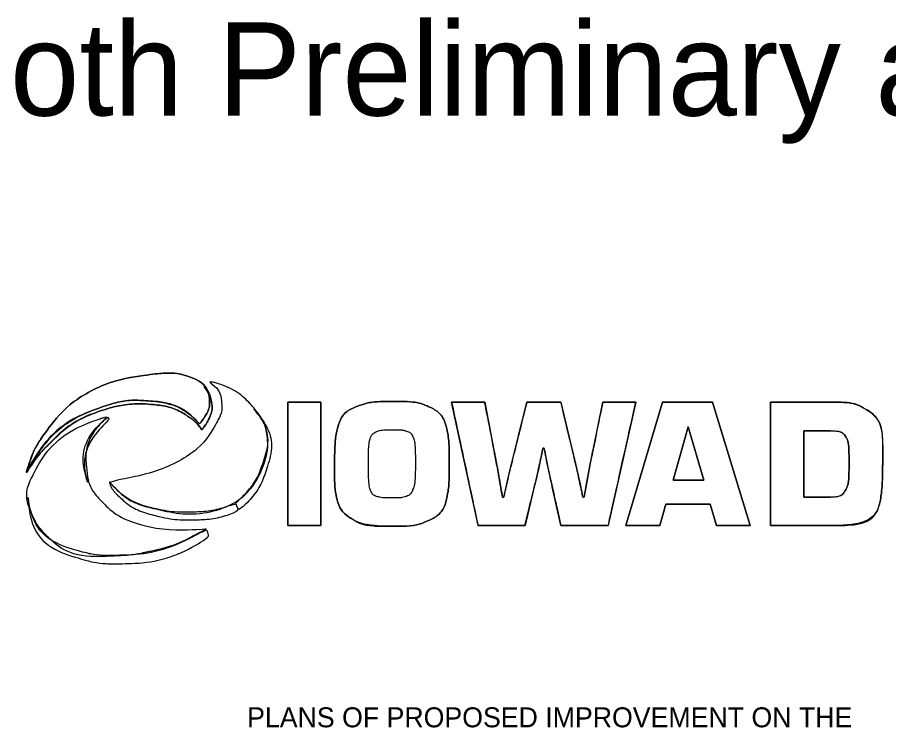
# Model space of a CAD drawing. Extents: x 10196 to 23010, y 6417 to 10189.
# Drawn here: x 11284 to 11939, y 9655 to 10189 of the extents above; entities that cross this region are included whole.
import ezdxf

# ---------------------------------------------------------------- set-up
doc = ezdxf.new("R2010")
doc.units = 0
doc.layers.add('dsnDOTLogo', color=7, linetype='Continuous')
doc.layers.add('Level 1', color=7, linetype='Continuous')

msp = doc.modelspace()

# ---------------------------------------------------------------- linework, layer by layer
at = {"layer": 'dsnDOTLogo'}
for p, q in [((11630.53, 9807.22), (11610.74, 9899.72)), ((11610.74, 9899.72), (11635.62, 9899.72)), ((11635.62, 9899.72), (11642.48, 9864.08)), ((11653.84, 9846.25), (11667.25, 9899.72)), ((11667.25, 9899.72), (11692.8, 9899.72)), ((11692.8, 9899.72), (11701.34, 9864.08)), ((11716.99, 9864.08), (11724.24, 9899.72)), ((11724.24, 9899.72), (11749.04, 9899.72)), ((11749.04, 9899.72), (11728.44, 9807.22)), ((11850.38, 9807.22), (11850.38, 9899.72)), ((11850.38, 9899.72), (11898.75, 9899.72)), ((11420.59, 9884.21), (11421.27, 9883.48)), ((11421.27, 9883.48), (11420.59, 9884.21)), ((11421.27, 9883.48), (11421.91, 9884.25)), ((11421.91, 9884.25), (11421.27, 9883.48)), ((11423.02, 9878.95), (11423.14, 9879.1)), ((11423.14, 9879.1), (11423.54, 9879.6)), ((11423.91, 9880.04), (11424.1, 9880.29)), ((11424.1, 9880.29), (11424.1, 9880.32)), ((11424.52, 9880.92), (11424.54, 9880.9)), ((11424.54, 9880.9), (11424.53, 9880.94)), ((11895.4, 9878.17), (11875.31, 9878.17)), ((11875.31, 9878.17), (11875.31, 9828.5)), ((11307.37, 9867.39), (11307.37, 9867.37)), ((11680.25, 9865.16), (11679.32, 9865.16)), ((11934.61, 9865.23), (11934.61, 9854.18)), ((11716.58, 9862.18), (11716.99, 9864.08)), ((11293.8, 9855.21), (11291.27, 9847.78)), ((11291.27, 9847.78), (11295.38, 9854.47)), ((11295.38, 9854.47), (11291.27, 9847.78)), ((11291.27, 9847.78), (11291.27, 9846.94)), ((11649.84, 9828.43), (11653.84, 9846.25)), ((11672.84, 9836.22), (11665.85, 9807.22)), ((11692.77, 9807.22), (11686.34, 9836.23)), ((11648.89, 9828.43), (11649.84, 9828.43)), ((11709.33, 9828.43), (11710.28, 9828.43)), ((11875.31, 9828.5), (11895.33, 9828.5)), ((11665.85, 9807.22), (11630.53, 9807.22)), ((11728.44, 9807.22), (11692.77, 9807.22)), ((11897.47, 9807.22), (11850.38, 9807.22))]:
    msp.add_line(p, q, dxfattribs=at)
for points in [[(11512.48, 9807.22), (11512.48, 9899.72), (11487.54, 9899.72), (11487.54, 9807.22), (11512.48, 9807.22)], [(11512.48, 9899.72), (11512.48, 9807.22), (11487.54, 9807.22), (11487.54, 9899.72), (11512.48, 9899.72)], [(11804.95, 9823.15), (11771.67, 9823.15), (11767.24, 9807.22), (11741.49, 9807.22), (11769.27, 9899.72), (11806.81, 9899.72), (11834.94, 9807.22), (11809.72, 9807.22), (11804.95, 9823.15)], [(11834.94, 9807.22), (11806.81, 9899.72), (11769.27, 9899.72), (11741.49, 9807.22), (11767.24, 9807.22), (11771.67, 9823.15), (11804.95, 9823.15), (11809.72, 9807.22), (11834.94, 9807.22)], [(11777.07, 9841.1), (11788.42, 9881.25), (11800.13, 9841.1), (11777.07, 9841.1)], [(11800.13, 9841.1), (11788.42, 9881.25), (11777.07, 9841.1), (11800.13, 9841.1)]]:
    msp.add_lwpolyline(points, dxfattribs=at)
for points, degree in [([(11408.05, 9920.61), (11402.55, 9921.77), (11394.73, 9921.8), (11385.55, 9920.67), (11353.84, 9916.5), (11321.5, 9898.71), (11305.08, 9876.41), (11300.05, 9869.58), (11296.26, 9862.44), (11293.8, 9855.21), (11293.8, 9855.21), (11291.27, 9847.78), (11291.27, 9847.78), (11291.27, 9847.78), (11295.38, 9854.47), (11295.38, 9854.47), (11306.66, 9872.85), (11325.79, 9888.23), (11346.55, 9895.62), (11358.24, 9899.79), (11370.7, 9901.62), (11382.08, 9900.82), (11397.68, 9899.74), (11411.72, 9893.68), (11420.59, 9884.21), (11420.59, 9884.21), (11421.27, 9883.48), (11421.27, 9883.48), (11421.27, 9883.48), (11421.91, 9884.25), (11421.91, 9884.25), (11423.3, 9885.94), (11424.49, 9887.63), (11425.45, 9889.26), (11427.91, 9893.41), (11429.05, 9897.51), (11428.83, 9901.52), (11427.94, 9910.33), (11420.38, 9917.29), (11408.05, 9920.61)], 3), ([(11408.05, 9920.61), (11402.55, 9921.77), (11394.73, 9921.8), (11385.55, 9920.67), (11353.84, 9916.5), (11321.5, 9898.71), (11305.08, 9876.41), (11300.05, 9869.58), (11296.26, 9862.44), (11293.8, 9855.21)], 3), ([(11421.91, 9884.25), (11423.3, 9885.94), (11424.49, 9887.63), (11425.45, 9889.26), (11427.91, 9893.41), (11429.05, 9897.51), (11428.83, 9901.52), (11427.94, 9910.33), (11420.38, 9917.29), (11408.05, 9920.61)], 3), ([(11429.91, 9901.61), (11429.91, 9901.61), (11429.12, 9907.3), (11423.22, 9912.63), (11426.46, 9909.47), (11428.41, 9905.71), (11428.83, 9901.52), (11429.05, 9897.51), (11427.91, 9893.41), (11425.45, 9889.26), (11424.49, 9887.63), (11423.3, 9885.94), (11421.91, 9884.25), (11421.91, 9884.25), (11421.27, 9883.48), (11421.27, 9883.48), (11421.27, 9883.48), (11420.59, 9884.21), (11420.59, 9884.21), (11411.72, 9893.68), (11397.68, 9899.74), (11382.08, 9900.82), (11370.7, 9901.62), (11358.24, 9899.79), (11346.55, 9895.62), (11325.79, 9888.23), (11306.66, 9872.85), (11295.38, 9854.47), (11295.38, 9854.47), (11291.27, 9847.78), (11291.27, 9847.78), (11291.27, 9847.78), (11291.27, 9846.94), (11291.27, 9846.94), (11291.27, 9846.94), (11300.26, 9860.62), (11307.37, 9867.39), (11307.37, 9867.39), (11307.37, 9867.37), (11307.37, 9867.37), (11318.04, 9878.55), (11331.79, 9887.9), (11347, 9893.23), (11352.61, 9895.19), (11358.22, 9896.6), (11363.71, 9897.45), (11370.58, 9898.51), (11377.3, 9898.74), (11383.69, 9898.21), (11395.52, 9897.22), (11406.41, 9893.47), (11415.07, 9887.49), (11415.96, 9886.79), (11419.92, 9883.56), (11423.02, 9878.95), (11423.02, 9878.95), (11423.14, 9879.1), (11423.14, 9879.1), (11423.14, 9879.1), (11423.54, 9879.6), (11423.54, 9879.6), (11423.55, 9879.59), (11423.55, 9879.58), (11423.56, 9879.57), (11423.68, 9879.73), (11423.79, 9879.88), (11423.91, 9880.04), (11423.91, 9880.04), (11424.1, 9880.29), (11424.1, 9880.29), (11424.1, 9880.29), (11424.1, 9880.32), (11424.1, 9880.32), (11424.25, 9880.52), (11424.38, 9880.72), (11424.52, 9880.92), (11424.52, 9880.92), (11424.54, 9880.9), (11424.54, 9880.9), (11424.54, 9880.9), (11424.53, 9880.94), (11424.53, 9880.94), (11425.45, 9882.23), (11426.31, 9883.52), (11427.03, 9884.83), (11430.37, 9890.84), (11431.24, 9896.57), (11429.91, 9901.61)], 3), ([(11469.85, 9853.83), (11466.08, 9843.07), (11458.77, 9832.97), (11448.77, 9823.93), (11429.81, 9816.48), (11408.33, 9815.06), (11389.33, 9819.38), (11376.53, 9822.3), (11365.46, 9827.73), (11357.58, 9835.58), (11355.99, 9837.13), (11354.61, 9838.76), (11353.36, 9840.44), (11389.24, 9846.17), (11423.04, 9864.23), (11434.79, 9885.6), (11437.36, 9890.29), (11438.33, 9894.85), (11437.88, 9899.05), (11437.43, 9906.05), (11433.09, 9912.13), (11425.63, 9916.37), (11441.55, 9912.25), (11454.42, 9904.45), (11462.42, 9894.95), (11467.98, 9888.34), (11471.45, 9880.48), (11472.3, 9872), (11472.76, 9866.17), (11472.01, 9860.04), (11469.85, 9853.83)], 3), ([(11469.85, 9853.83), (11466.08, 9843.07), (11458.77, 9832.97), (11448.77, 9823.93), (11429.81, 9816.48), (11408.33, 9815.06), (11389.33, 9819.38), (11376.53, 9822.3), (11365.46, 9827.73), (11357.58, 9835.58), (11355.99, 9837.13), (11354.61, 9838.76), (11353.36, 9840.44), (11389.24, 9846.17), (11423.04, 9864.23), (11434.79, 9885.6), (11437.36, 9890.29), (11438.33, 9894.85), (11437.88, 9899.05), (11437.43, 9906.05), (11433.09, 9912.13), (11425.63, 9916.37), (11441.55, 9912.25), (11454.42, 9904.45), (11462.42, 9894.95), (11467.98, 9888.34), (11471.45, 9880.48), (11472.3, 9872), (11472.76, 9866.17), (11472.01, 9860.04), (11469.85, 9853.83)], 3), ([(11429.91, 9901.61), (11429.91, 9901.61), (11429.12, 9907.3), (11423.22, 9912.63), (11426.46, 9909.47), (11428.41, 9905.71), (11428.83, 9901.52), (11429.05, 9897.51), (11427.91, 9893.41), (11425.45, 9889.26), (11424.49, 9887.63), (11423.3, 9885.94), (11421.91, 9884.25)], 3), ([(11295.38, 9854.47), (11306.66, 9872.85), (11325.79, 9888.23), (11346.55, 9895.62), (11358.24, 9899.79), (11370.7, 9901.62), (11382.08, 9900.82), (11397.68, 9899.74), (11411.72, 9893.68), (11420.59, 9884.21)], 3), ([(11420.59, 9884.21), (11411.72, 9893.68), (11397.68, 9899.74), (11382.08, 9900.82), (11370.7, 9901.62), (11358.24, 9899.79), (11346.55, 9895.62), (11325.79, 9888.23), (11306.66, 9872.85), (11295.38, 9854.47)], 3), ([(11307.37, 9867.37), (11318.04, 9878.55), (11331.79, 9887.9), (11347, 9893.23), (11352.61, 9895.19), (11358.22, 9896.6), (11363.71, 9897.45), (11370.58, 9898.51), (11377.3, 9898.74), (11383.69, 9898.21), (11395.52, 9897.22), (11406.41, 9893.47), (11415.07, 9887.49), (11415.96, 9886.79), (11419.92, 9883.56), (11423.02, 9878.95)], 3), ([(11424.53, 9880.94), (11425.45, 9882.23), (11426.31, 9883.52), (11427.03, 9884.83), (11430.37, 9890.84), (11431.24, 9896.57), (11429.91, 9901.61)], 3), ([(11550.16, 9807.39), (11544.37, 9808.2), (11539.86, 9809.59), (11536.64, 9811.56), (11529.68, 9815.85), (11525.39, 9822.24), (11523.76, 9830.74), (11523.09, 9834.3), (11522.75, 9840.25), (11522.75, 9848.56), (11522.75, 9864.1), (11523.56, 9874.78), (11525.19, 9880.61), (11527.45, 9888.7), (11533.39, 9894.43), (11543.01, 9897.82), (11547.8, 9899.54), (11555.88, 9900.4), (11567.27, 9900.4)], 3), ([(11567.27, 9900.4), (11578.65, 9900.4), (11586.78, 9899.33), (11591.66, 9897.21), (11600.34, 9893.42), (11605.67, 9886.66), (11607.65, 9876.95), (11608.47, 9872.97), (11608.87, 9864.98), (11608.87, 9852.96), (11608.87, 9842.89), (11608.56, 9836), (11607.93, 9832.29), (11606.12, 9821.72), (11601.1, 9814.52), (11592.88, 9810.68), (11587.01, 9807.92), (11577.43, 9806.54), (11564.15, 9806.54), (11551.28, 9806.54), (11542.11, 9808.22), (11536.64, 9811.56), (11529.68, 9815.85), (11525.39, 9822.24), (11523.76, 9830.74), (11523.09, 9834.3), (11522.75, 9840.25), (11522.75, 9848.56), (11522.75, 9864.1), (11523.56, 9874.78), (11525.19, 9880.61), (11527.45, 9888.7), (11533.39, 9894.43), (11543.01, 9897.82), (11547.8, 9899.54), (11555.88, 9900.4), (11567.27, 9900.4)], 3), ([(11567.27, 9900.4), (11578.65, 9900.4), (11586.78, 9899.33), (11591.66, 9897.21), (11600.34, 9893.42), (11605.67, 9886.66), (11607.65, 9876.95), (11608.47, 9872.97), (11608.87, 9864.98), (11608.87, 9852.96), (11608.87, 9842.89), (11608.56, 9836), (11607.93, 9832.29), (11606.12, 9821.72), (11601.1, 9814.52), (11592.88, 9810.68), (11587.01, 9807.92), (11577.43, 9806.54), (11564.15, 9806.54), (11558.86, 9806.54), (11554.2, 9806.83), (11550.16, 9807.39)], 3), ([(11749.04, 9899.72), (11749.04, 9899.72), (11728.44, 9807.22), (11728.44, 9807.22), (11728.44, 9807.22), (11692.77, 9807.22), (11692.77, 9807.22), (11692.77, 9807.22), (11686.34, 9836.23), (11686.34, 9836.23), (11684.38, 9844.95), (11682.34, 9854.59), (11680.25, 9865.16), (11680.25, 9865.16), (11679.32, 9865.16), (11679.32, 9865.16), (11678.65, 9862.17), (11678.14, 9859.75), (11677.79, 9857.9), (11676.97, 9853.79), (11675.32, 9846.56), (11672.84, 9836.22), (11672.84, 9836.22), (11665.85, 9807.22), (11665.85, 9807.22), (11665.85, 9807.22), (11630.53, 9807.22), (11630.53, 9807.22), (11630.53, 9807.22), (11610.74, 9899.72), (11610.74, 9899.72), (11610.74, 9899.72), (11635.62, 9899.72), (11635.62, 9899.72), (11635.62, 9899.72), (11642.48, 9864.08), (11642.48, 9864.08), (11644.87, 9851.57), (11647, 9839.68), (11648.89, 9828.43), (11648.89, 9828.43), (11649.84, 9828.43), (11649.84, 9828.43), (11649.84, 9828.43), (11653.84, 9846.25), (11653.84, 9846.25), (11653.84, 9846.25), (11667.25, 9899.72), (11667.25, 9899.72), (11667.25, 9899.72), (11692.8, 9899.72), (11692.8, 9899.72), (11692.8, 9899.72), (11701.34, 9864.08), (11701.34, 9864.08), (11704.09, 9852.6), (11706.76, 9840.72), (11709.33, 9828.43), (11709.33, 9828.43), (11710.28, 9828.43), (11710.28, 9828.43), (11712.23, 9839.68), (11714.32, 9850.93), (11716.58, 9862.18), (11716.58, 9862.18), (11716.99, 9864.08), (11716.99, 9864.08), (11716.99, 9864.08), (11724.24, 9899.72), (11724.24, 9899.72), (11724.24, 9899.72), (11749.04, 9899.72), (11749.04, 9899.72)], 3), ([(11850.38, 9807.22), (11850.38, 9807.22), (11850.38, 9899.72), (11850.38, 9899.72), (11850.38, 9899.72), (11898.75, 9899.72), (11898.75, 9899.72), (11908.36, 9899.72), (11915.77, 9898.14), (11921.01, 9894.98), (11930.25, 9889.42), (11934.78, 9879.5), (11934.61, 9865.23), (11934.61, 9865.23), (11934.61, 9854.18), (11934.61, 9854.18), (11934.47, 9842.84), (11934.13, 9835.21), (11933.59, 9831.28), (11931.42, 9815.24), (11919.38, 9807.22), (11897.47, 9807.22), (11897.47, 9807.22), (11850.38, 9807.22), (11850.38, 9807.22)], 3), ([(11898.75, 9899.72), (11908.36, 9899.72), (11915.77, 9898.14), (11921.01, 9894.98), (11930.25, 9889.42), (11934.78, 9879.5), (11934.61, 9865.23)], 3), ([(11448.41, 9823.99), (11449.24, 9822.1), (11450.05, 9820.17), (11450.87, 9818.25), (11460.76, 9827.66), (11467.95, 9838.16), (11471.57, 9849.32), (11476.73, 9865.25), (11473.38, 9880.46), (11464.11, 9892.11), (11463.26, 9893.19), (11462.41, 9894.26), (11461.54, 9895.28), (11470.76, 9884.19), (11474.1, 9869.6), (11469.02, 9854.25), (11465.42, 9843.42), (11458.25, 9833.2), (11448.41, 9823.99), (11448.41, 9823.99), (11448.41, 9823.99), (11448.41, 9823.99)], 3), ([(11448.41, 9823.99), (11449.24, 9822.1), (11450.05, 9820.17), (11450.87, 9818.25), (11460.76, 9827.66), (11467.95, 9838.16), (11471.57, 9849.32), (11476.73, 9865.25), (11473.38, 9880.46), (11464.11, 9892.11), (11463.26, 9893.19), (11462.41, 9894.26), (11461.54, 9895.28), (11470.76, 9884.19), (11474.1, 9869.6), (11469.02, 9854.25), (11465.42, 9843.42), (11458.25, 9833.2), (11448.41, 9823.99), (11448.41, 9823.99), (11448.41, 9823.99), (11448.41, 9823.99)], 3), ([(11383.83, 9806.15), (11369.29, 9809.54), (11356.81, 9815.85), (11348.07, 9824.95), (11340.83, 9832.49), (11336.99, 9841.41), (11336.37, 9850.64), (11335.22, 9863.87), (11340.75, 9877.77), (11352.42, 9889.13), (11350.26, 9888.56), (11348.09, 9887.89), (11345.91, 9887.11), (11325.09, 9879.74), (11305.84, 9863.9), (11295.72, 9844.08), (11290.76, 9834.37), (11291.79, 9823.18), (11296.36, 9813.52), (11297.85, 9810.37), (11299.77, 9806.93), (11302.07, 9804.29), (11310.62, 9794.49), (11327.37, 9783.04), (11358.63, 9784.27), (11360.79, 9784.35), (11363.03, 9784.52), (11365.33, 9784.71), (11365.33, 9784.71), (11371.12, 9784.98), (11380.22, 9786.84), (11380.36, 9786.86), (11380.49, 9786.89), (11380.64, 9786.91), (11380.64, 9786.91), (11380.83, 9786.96), (11381.17, 9787.04), (11391.35, 9789.19), (11405.34, 9793.27), (11419.93, 9801), (11422.16, 9802.14), (11424.34, 9803.36), (11426.41, 9804.63), (11426.41, 9804.63), (11396.63, 9803.19), (11383.83, 9806.15)], 3), ([(11383.83, 9806.15), (11369.29, 9809.54), (11356.81, 9815.85), (11348.07, 9824.95), (11340.83, 9832.49), (11336.99, 9841.41), (11336.37, 9850.64), (11335.22, 9863.87), (11340.75, 9877.77), (11352.42, 9889.13), (11350.26, 9888.56), (11348.09, 9887.89), (11345.91, 9887.11), (11325.09, 9879.74), (11305.84, 9863.9), (11295.72, 9844.08), (11290.76, 9834.37), (11291.79, 9823.18), (11296.36, 9813.52), (11297.85, 9810.37), (11299.77, 9806.93), (11302.07, 9804.29), (11310.62, 9794.49), (11327.37, 9783.04), (11358.63, 9784.27), (11360.79, 9784.35), (11363.03, 9784.52), (11365.33, 9784.71), (11365.33, 9784.71), (11371.12, 9784.98), (11380.22, 9786.84), (11380.36, 9786.86), (11380.49, 9786.89), (11380.64, 9786.91), (11380.64, 9786.91), (11380.83, 9786.96), (11381.17, 9787.04), (11391.35, 9789.19), (11405.34, 9793.27), (11419.93, 9801), (11422.16, 9802.14), (11424.34, 9803.36), (11426.41, 9804.63), (11426.41, 9804.63), (11396.63, 9803.19), (11383.83, 9806.15)], 3), ([(11336.16, 9843.32), (11336.57, 9841.78), (11336.96, 9840.21), (11337.4, 9838.64), (11333.14, 9854.36), (11338.76, 9872.34), (11353.36, 9886.36), (11353.05, 9887.29), (11352.76, 9888.22), (11352.45, 9889.13), (11337.97, 9875.67), (11332.22, 9858.38), (11336.16, 9843.32), (11336.16, 9843.32), (11336.16, 9843.32), (11336.16, 9843.32)], 3), ([(11336.16, 9843.32), (11336.57, 9841.78), (11336.96, 9840.21), (11337.4, 9838.64), (11333.14, 9854.36), (11338.76, 9872.34), (11353.36, 9886.36), (11353.05, 9887.29), (11352.76, 9888.22), (11352.45, 9889.13), (11337.97, 9875.67), (11332.22, 9858.38), (11336.16, 9843.32), (11336.16, 9843.32), (11336.16, 9843.32), (11336.16, 9843.32)], 3), ([(11423.54, 9879.6), (11423.55, 9879.59), (11423.55, 9879.58), (11423.56, 9879.57), (11423.68, 9879.73), (11423.79, 9879.88), (11423.91, 9880.04)], 3), ([(11424.1, 9880.32), (11424.25, 9880.52), (11424.38, 9880.72), (11424.52, 9880.92)], 2), ([(11566.52, 9879.12), (11560.79, 9879.16), (11556.85, 9878.73), (11554.73, 9877.83), (11551.25, 9876.38), (11549.15, 9872.55), (11548.43, 9866.31), (11548.3, 9865.27), (11548.23, 9860.53), (11548.23, 9852.08), (11548.23, 9842.55), (11548.77, 9836.36), (11549.85, 9833.51), (11550.89, 9830.85), (11553.24, 9829.13), (11556.9, 9828.36), (11558.62, 9828), (11561.73, 9827.82), (11566.25, 9827.82), (11570.59, 9827.82), (11573.62, 9828.07), (11575.33, 9828.57), (11578.36, 9829.47), (11580.47, 9831.45), (11581.67, 9834.5), (11582.86, 9837.54), (11583.46, 9844.2), (11583.46, 9854.45), (11583.46, 9864.53), (11582.9, 9870.86), (11581.77, 9873.46), (11580.64, 9876.06), (11578.47, 9877.74), (11575.26, 9878.51), (11573.64, 9878.92), (11570.72, 9879.12), (11566.52, 9879.12)], 3), ([(11566.52, 9879.12), (11560.79, 9879.16), (11556.85, 9878.73), (11554.73, 9877.83), (11551.25, 9876.38), (11549.15, 9872.55), (11548.43, 9866.31), (11548.3, 9865.27), (11548.23, 9860.53), (11548.23, 9852.08), (11548.23, 9842.55), (11548.77, 9836.36), (11549.85, 9833.51), (11550.89, 9830.85), (11553.24, 9829.13), (11556.9, 9828.36), (11558.62, 9828), (11561.73, 9827.82), (11566.25, 9827.82), (11570.59, 9827.82), (11573.62, 9828.07), (11575.33, 9828.57), (11578.36, 9829.47), (11580.47, 9831.45), (11581.67, 9834.5), (11582.86, 9837.54), (11583.46, 9844.2), (11583.46, 9854.45), (11583.46, 9864.53), (11582.9, 9870.86), (11581.77, 9873.46), (11580.64, 9876.06), (11578.47, 9877.74), (11575.26, 9878.51), (11573.64, 9878.92), (11570.72, 9879.12), (11566.52, 9879.12)], 3), ([(11875.31, 9828.5), (11875.31, 9828.5), (11895.33, 9828.5), (11895.33, 9828.5), (11900.96, 9828.5), (11904.8, 9830.28), (11906.83, 9833.85), (11908.49, 9836.79), (11909.33, 9843.77), (11909.33, 9854.79), (11909.33, 9864.82), (11908.52, 9871.15), (11906.9, 9873.77), (11905.05, 9876.7), (11901.21, 9878.17), (11895.4, 9878.17), (11895.4, 9878.17), (11875.31, 9878.17), (11875.31, 9878.17), (11875.31, 9878.17), (11875.31, 9828.5), (11875.31, 9828.5)], 3), ([(11895.33, 9828.5), (11900.96, 9828.5), (11904.8, 9830.28), (11906.83, 9833.85), (11908.49, 9836.79), (11909.33, 9843.77), (11909.33, 9854.79), (11909.33, 9864.82), (11908.52, 9871.15), (11906.9, 9873.77), (11905.05, 9876.7), (11901.21, 9878.17), (11895.4, 9878.17)], 3), ([(11291.27, 9846.94), (11291.27, 9846.94), (11300.26, 9860.62), (11307.37, 9867.39)], 2), ([(11679.32, 9865.16), (11678.65, 9862.17), (11678.14, 9859.75), (11677.79, 9857.9), (11676.97, 9853.79), (11675.32, 9846.56), (11672.84, 9836.22)], 3), ([(11686.34, 9836.23), (11684.38, 9844.95), (11682.34, 9854.59), (11680.25, 9865.16)], 2), ([(11642.48, 9864.08), (11644.87, 9851.57), (11647, 9839.68), (11648.89, 9828.43)], 2), ([(11701.34, 9864.08), (11704.09, 9852.6), (11706.76, 9840.72), (11709.33, 9828.43)], 2), ([(11710.28, 9828.43), (11712.23, 9839.68), (11714.32, 9850.93), (11716.58, 9862.18)], 2), ([(11934.61, 9854.18), (11934.47, 9842.84), (11934.13, 9835.21), (11933.59, 9831.28), (11931.42, 9815.24), (11919.38, 9807.22), (11897.47, 9807.22)], 3), ([(11358.04, 9835.1), (11365.85, 9827.51), (11376.84, 9822.26), (11389.54, 9819.45), (11396.77, 9817.85), (11404.45, 9817.07), (11412.29, 9817.15), (11424.67, 9817.27), (11437.13, 9819.47), (11448.53, 9823.83), (11449.34, 9821.99), (11450.11, 9820.12), (11450.9, 9818.25), (11439.51, 9813.77), (11427.03, 9811.51), (11414.61, 9811.4), (11406.74, 9811.33), (11399.03, 9812.13), (11391.76, 9813.78), (11378.92, 9816.7), (11367.77, 9822.15), (11359.76, 9829.99), (11357.94, 9831.75), (11356.35, 9833.61), (11354.96, 9835.52), (11354.42, 9837.17), (11353.9, 9838.81), (11353.36, 9840.44), (11354.72, 9838.58), (11356.26, 9836.8), (11358.04, 9835.1)], 3), ([(11358.04, 9835.1), (11365.85, 9827.51), (11376.84, 9822.26), (11389.54, 9819.45), (11396.77, 9817.85), (11404.45, 9817.07), (11412.29, 9817.15), (11424.67, 9817.27), (11437.13, 9819.47), (11448.53, 9823.83), (11449.34, 9821.99), (11450.11, 9820.12), (11450.9, 9818.25), (11439.51, 9813.77), (11427.03, 9811.51), (11414.61, 9811.4), (11406.74, 9811.33), (11399.03, 9812.13), (11391.76, 9813.78), (11378.92, 9816.7), (11367.77, 9822.15), (11359.76, 9829.99), (11357.94, 9831.75), (11356.35, 9833.61), (11354.96, 9835.52), (11354.42, 9837.17), (11353.9, 9838.81), (11353.36, 9840.44), (11354.72, 9838.58), (11356.26, 9836.8), (11358.04, 9835.1)], 3), ([(11292.55, 9828.31), (11294.76, 9809.93), (11307.84, 9794.45), (11330.76, 9787.99), (11339.48, 9785.55), (11348.94, 9784.5), (11358.81, 9784.72), (11381.99, 9785.25), (11405.92, 9792.52), (11426.43, 9804.65), (11427.22, 9802.57), (11427.97, 9800.46), (11428.74, 9798.36), (11408.24, 9786.07), (11384.24, 9778.81), (11360.92, 9778.45), (11350.97, 9778.31), (11341.39, 9779.45), (11332.54, 9782.02), (11308.28, 9789.11), (11294.54, 9806.16), (11292.66, 9826.05), (11292.61, 9826.83), (11292.57, 9827.58), (11292.55, 9828.31)], 3), ([(11292.55, 9828.31), (11294.76, 9809.93), (11307.84, 9794.45), (11330.76, 9787.99), (11339.48, 9785.55), (11348.94, 9784.5), (11358.81, 9784.72), (11381.99, 9785.25), (11405.92, 9792.52), (11426.43, 9804.65), (11427.22, 9802.57), (11427.97, 9800.46), (11428.74, 9798.36), (11408.24, 9786.07), (11384.24, 9778.81), (11360.92, 9778.45), (11350.97, 9778.31), (11341.39, 9779.45), (11332.54, 9782.02), (11308.28, 9789.11), (11294.54, 9806.16), (11292.66, 9826.05), (11292.61, 9826.83), (11292.57, 9827.58), (11292.55, 9828.31)], 3)]:
    msp.add_open_spline(points, degree=degree, dxfattribs=at)

# ---------------------------------------------------------------- texts
at = {"layer": 'Level 1'}
for s, height, p in [('Title Sheet, both Preliminary and Final', 70, (10727.37, 10115)), ('PLANS OF PROPOSED IMPROVEMENT ON THE', 15, (11457.05, 9655.62))]:
    msp.add_text(s, height=height, dxfattribs=at).set_placement(p)

doc.saveas('drawing.dxf')
